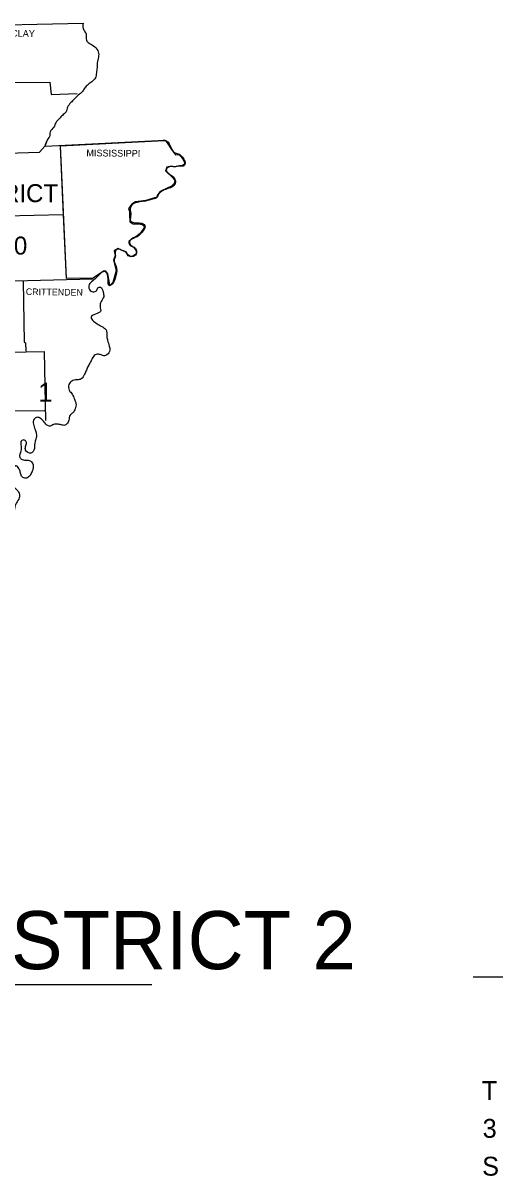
# Model space of a CAD drawing. Extents: x -42408 to 34530, y -43140 to 20491.
# Drawn here: x 4174 to 5698, y -23873 to -20216 of the extents above; entities that cross this region are included whole.
import ezdxf

# ---------------------------------------------------------------- set-up
doc = ezdxf.new("R2010")
doc.units = 0
for name, color, linetype in [('1', 7, 'Continuous'), ('2', 7, 'Continuous'), ('3', 7, 'Continuous'), ('Default', 7, 'Continuous')]:
    doc.layers.add(name, color=color, linetype=linetype)

msp = doc.modelspace()

# ---------------------------------------------------------------- linework, layer by layer
at = {"layer": '1'}
for p, q in [((4244.5, -20607.1), (4250.5, -20588.6)), ((4246, -20601.1), (4252, -20586.6)), ((4292.9, -20605.3), (4622.3, -20589)), ((4622.3, -20589), (4625.1, -20588.9)), ((4625.1, -20588.9), (4627.5, -20590.5)), ((4627.5, -20590.5), (4633.8, -20599.7)), ((4312.5, -21026.2), (4292.9, -20605.3)), ((4633.8, -20599.7), (4645.8, -20617)), ((4645.8, -20617), (4657.8, -20634.3)), ((4657.8, -20634.3), (4663.8, -20632.6)), ((4663.8, -20632.6), (4670, -20633.7)), ((4670, -20633.7), (4675.5, -20639.3)), ((4675.5, -20639.3), (4681.8, -20647.7)), ((4681.8, -20647.7), (4686.5, -20656.9)), ((4686.5, -20656.9), (4686.6, -20664)), ((4629.1, -20676.1), (4626.7, -20685.3)), ((4626.7, -20685.3), (4650.8, -20707.7)), ((4631.1, -20673.3), (4629.1, -20676.1)), ((4644, -20670.5), (4631.1, -20673.3)), ((4654.6, -20671.7), (4644, -20670.5)), ((4670.7, -20668.5), (4654.6, -20671.7)), ((4680.4, -20668.4), (4670.7, -20668.5)), ((4686.6, -20664), (4680.4, -20668.4)), ((4645.9, -20733.8), (4613.3, -20748.2)), ((4654.1, -20725.5), (4645.9, -20733.8)), ((4650.8, -20707.7), (4656.3, -20715.9)), ((4656.3, -20715.9), (4654.1, -20725.5)), ((4598.5, -20768.7), (4564.5, -20779.4)), ((4601, -20761.3), (4598.5, -20768.7)), ((4606.9, -20753.7), (4601, -20761.3)), ((4613.3, -20748.2), (4606.9, -20753.7)), ((4519.5, -20790.2), (4509.5, -20804.3)), ((4509.5, -20804.3), (4512.6, -20813.5)), ((4530.9, -20783), (4519.5, -20790.2)), ((4564.5, -20779.4), (4530.9, -20783)), ((4512.6, -20813.5), (4512.6, -20823.1)), ((4512.6, -20823.1), (4513.5, -20847)), ((4513.5, -20847), (4523.6, -20853)), ((4523.6, -20853), (4535.3, -20853.4)), ((4535.3, -20853.4), (4547, -20853.8)), ((4560.1, -20863.4), (4545.8, -20883.9)), ((4547, -20853.8), (4551.3, -20853.9)), ((4551.3, -20853.9), (4556.8, -20858)), ((4556.8, -20858), (4560.1, -20863.4)), ((4523.5, -20897.9), (4510, -20908.8)), ((4510, -20908.8), (4510.5, -20913.9)), ((4510.5, -20913.9), (4514.6, -20921.7)), ((4532.3, -20894.1), (4523.5, -20897.9)), ((4545.8, -20883.9), (4532.3, -20894.1)), ((4466.2, -20953.4), (4461.1, -20967.9)), ((4475.7, -20931.3), (4463.8, -20939)), ((4463.8, -20939), (4464.4, -20944.8)), ((4464.4, -20944.8), (4466.2, -20953.4)), ((4487.1, -20936), (4475.7, -20931.3)), ((4501.9, -20942.1), (4487.1, -20936)), ((4506.8, -20951), (4501.9, -20942.1)), ((4515.7, -20956.1), (4506.8, -20951)), ((4514.6, -20921.7), (4524.5, -20927.2)), ((4522.8, -20955.8), (4515.7, -20956.1)), ((4531.7, -20950), (4522.8, -20955.8)), ((4524.5, -20927.2), (4532.1, -20936.3)), ((4534.7, -20943.6), (4531.7, -20950)), ((4532.1, -20936.3), (4534.7, -20943.6)), ((4461.1, -20967.9), (4470, -21001.1)), ((4397.1, -21025.6), (4312.5, -21026.2)), ((4429.3, -21002.7), (4397.1, -21025.6)), ((4436.5, -21003.2), (4429.3, -21002.7)), ((4443.1, -21011.3), (4436.5, -21003.2)), ((4449.3, -21047.7), (4443.1, -21011.3)), ((4470, -21001.1), (4459.5, -21038.6)), ((4452.1, -21046.7), (4449.3, -21047.7)), ((4459.5, -21038.6), (4452.1, -21046.7))]:
    msp.add_line(p, q, dxfattribs=at)
for points in [[(1618, -20239.1), (2427.6, -20239.6), (3138, -20238.1), (3976.1, -20225.1), (4364.6, -20216.1)], [(3964, -20497.1), (3966.6, -20405.3), (3966.6, -20405.3), (4259.5, -20403.8), (4263.5, -20442.9), (4346.1, -20439.9)], [(4244.5, -20607.1), (4624.5, -20587.6)], [(3949.1, -20634.6), (4227, -20625.6), (4243.5, -20606.6)], [(4292.5, -20607.6), (4301.1, -20824.4), (4311.1, -21026.1)], [(4301.1, -20824.4), (3839.9, -20834.9)], [(3843.9, -21037.7), (4037.2, -21036.7), (4037.7, -21029.7), (4104.8, -21024.6), (4104.8, -21035.2), (4396.2, -21027.1)], [(4174.9, -21035.2), (4177.4, -21227.9), (4181.9, -21230.9), (4183.4, -21257)], [(3843.9, -21265.5), (4241.5, -21257.5)], [(4241.5, -21257.5), (4245.5, -21476.7)], [(3843.9, -21891.3), (3883, -21888.8), (3882.5, -21787.2), (3845.9, -21784.7), (3847.9, -21585.9), (3816.4, -21581.4), (3815.4, -21447.7), (4242.5, -21444.7)]]:
    msp.add_lwpolyline(points, dxfattribs=at)
for points in [[(4364.6, -20216.1), (4367.1, -20238.1), (4374.1, -20249.6), (4375.2, -20270.6), (4383.7, -20279.6), (4398.2, -20288.7), (4411.2, -20303.2), (4414.2, -20320.2), (4410.2, -20337.7), (4409.2, -20357.3), (4407.2, -20374.3), (4404.2, -20389.8), (4392.2, -20402.3), (4380.7, -20411.3), (4370.1, -20421.8), (4362.6, -20432.9), (4349.6, -20444.9), (4336.6, -20457.4), (4326.1, -20468.4), (4315.6, -20482.4), (4310.6, -20497.9), (4299, -20509), (4290, -20519), (4278, -20532.5), (4272, -20546), (4260.5, -20561.5), (4258, -20576.5), (4250.5, -20588.6), (4250, -20590.6)], [(4619, -20588.1), (4624.5, -20587.6), (4641.5, -20605.6), (4649, -20620.6), (4660, -20629.1), (4672.5, -20633.6), (4682.1, -20645.1), (4688.6, -20657.7), (4685.1, -20668.7), (4671, -20669.7), (4655.5, -20672.2), (4640.5, -20671.7), (4628.5, -20681.7), (4639.5, -20695.2), (4654, -20707.7), (4658, -20721.2), (4650, -20734.3), (4634, -20741.3), (4618.5, -20747.3), (4604.5, -20759.3), (4597.9, -20770.8), (4582.4, -20775.8), (4566.4, -20780.3), (4552.4, -20781.8), (4536.4, -20784.8), (4520.8, -20792.3), (4514.3, -20805.4), (4516.3, -20823.9), (4515.8, -20843.4), (4532.4, -20849.9), (4546.9, -20850.4), (4560.9, -20857.9), (4559.4, -20868.9), (4548.9, -20883), (4536.4, -20894), (4523.8, -20899.5), (4512.3, -20910), (4516.3, -20920.5), (4526.9, -20927.5), (4534.4, -20939), (4533.4, -20949.5), (4521.3, -20957.1), (4508.3, -20954), (4498.8, -20941.5), (4487.8, -20937.5), (4478.3, -20933), (4467.3, -20939.5), (4467.3, -20954), (4463.3, -20969.6), (4466.8, -20981.1), (4471.3, -20997.1), (4470.8, -21009.1), (4466.8, -21026.1), (4458.3, -21043.7), (4448.2, -21049.2), (4444.2, -21030.2), (4442.2, -21014.6), (4436.2, -21005.6), (4428.2, -21005.1), (4417.7, -21012.6), (4406.2, -21024.1), (4391.7, -21036.7), (4383.2, -21049.2), (4387.7, -21064.7), (4398.7, -21068.7), (4407.2, -21065.7), (4411.7, -21055.7), (4420.2, -21054.2), (4428.2, -21069.7)], [(4428.2, -21069.7), (4430.2, -21084.2), (4421.7, -21099.7), (4418.7, -21115.3), (4420.2, -21130.8), (4404.2, -21139.3), (4390.2, -21149.3), (4398.2, -21161.3), (4413.2, -21172.3), (4428.2, -21180.9), (4437.7, -21189.4), (4440.2, -21209.9), (4442.7, -21222.9), (4447.7, -21240.9), (4449.8, -21253.4), (4440.7, -21268.5), (4430.2, -21271.5), (4419.2, -21268), (4406.2, -21267), (4395.7, -21277), (4388.2, -21291), (4380.7, -21305), (4375.2, -21317), (4369.6, -21330.1), (4358.6, -21345.1), (4345.1, -21347.6), (4329.1, -21351.6), (4319.6, -21362.6), (4321.1, -21381.1), (4330.1, -21393.6), (4337.1, -21409.2), (4342.1, -21422.7), (4339.6, -21439.7), (4332.6, -21452.2), (4323.6, -21459.7), (4319.6, -21475.7), (4313.1, -21487.8), (4307.1, -21491.8), (4295, -21490.8), (4282, -21488.3), (4271, -21489.3), (4260.5, -21494.8), (4250, -21491.3), (4239, -21479.3), (4230, -21470.2), (4219.9, -21466.7), (4209.4, -21472.2), (4207.4, -21488.8), (4212.4, -21505.8), (4216.9, -21528.8), (4212.4, -21542.8), (4210.9, -21565.9)], [(4210.9, -21565.9), (4199.4, -21580.4), (4182.4, -21571.4), (4182.4, -21559.4), (4184.9, -21546.8), (4178.9, -21538.8), (4168.4, -21542.3), (4168.4, -21557.9), (4167.4, -21572.9), (4164.4, -21594.4), (4171.4, -21600.9), (4187.4, -21602.9), (4198.9, -21605.9), (4205.9, -21617.4), (4205.4, -21631.5), (4199.9, -21645), (4191.9, -21656), (4179.4, -21660), (4169.4, -21653.5), (4165.4, -21640.5), (4160.9, -21628.9), (4152.4, -21620.4), (4143.3, -21630), (4141.3, -21647.5), (4141.8, -21662.5), (4141.8, -21683), (4154.9, -21696.5), (4162.9, -21712.1), (4160.4, -21726.1), (4150.9, -21742.6), (4146.8, -21757.1), (4142.8, -21776.6), (4143.3, -21798.2), (4139.8, -21819.2), (4132.8, -21833.2), (4119.8, -21844.7), (4111.3, -21852.2), (4104.3, -21859.8), (4100.8, -21874.8), (4098.3, -21885.3), (4088.8, -21897.8), (4081.3, -21898.8), (4075.3, -21893.8), (4073.2, -21885.3), (4073.2, -21876.8), (4069.2, -21868.3), (4056.7, -21864.8), (4046.7, -21865.3), (4042.2, -21872.3), (4048.7, -21891.8), (4051.2, -21904.3), (4047.7, -21921.3), (4049.7, -21923.3), (4031.7, -21932.9), (4017.2, -21934.4), (4005.2, -21937.9), (3993.6, -21945.4), (3988.1, -21956.4), (3980.1, -21965.4), (3973.1, -21973.9), (3963.6, -21977.9), (3953.1, -21975.9), (3939.1, -21974.4), (3931.1, -21984.4), (3933.6, -21998.9), (3943.1, -22007.5), (3957.1, -22011.5), (3971.6, -22010.5), (3985.6, -22009), (3998.6, -22016), (3996.1, -22029.5), (3983.6, -22036), (3965.1, -22038), (3950.1, -22036.5), (3932.1, -22040.5), (3923, -22052), (3928.1, -22069.5), (3947.6, -22076.5), (3956.6, -22093.1), (3957.1, -22108.6), (3950.6, -22129.1), (3941.6, -22138.6), (3924, -22142.6), (3910.5, -22145.1), (3908.5, -22168.2), (3902.5, -22179.7), (3892, -22183.2), (3877, -22175.7), (3868, -22172.2), (3857, -22167.2), (3842.9, -22158.7), (3832.4, -22160.2), (3835.4, -22182.2), (3836.4, -22183.2), (3848.4, -22199.7), (3860.5, -22212.7), (3866, -22228.2)]]:
    msp.add_spline(points, degree=3, dxfattribs=at)
at = {"layer": '2'}
msp.add_line((1233.5, -23266.2), (4582.8, -23266.2), dxfattribs=at)
at = {"layer": 'Default'}
msp.add_line((5697.6, -23243.2), (5602.6, -23243.2), dxfattribs=at)

# ---------------------------------------------------------------- texts
at = {"layer": '1'}
msp.add_text('1', height=60.1, dxfattribs=at).set_placement((4222.9, -21417.2))
at = {"layer": '2'}
for s, height, rotation, p in [('CLAY', 21.52, 359.2258, (4136.3, -20259.1)), ('MISSISSIPPI', 21.524, 359.3097, (4375.2, -20638.6)), ('CRITTENDEN', 21.03, 359.213, (4182.9, -21078.7))]:
    msp.add_text(s, height=height, rotation=rotation, dxfattribs=at).set_placement(p)
for s, height, p in [('ARKANSAS HIGHWAY DISTRICT 2', 184.218, (1233.5, -23217.5)), ('T', 60, (5630.5, -23632.5)), ('3', 60, (5633.1, -23752.5)), ('S', 60, (5631.6, -23872.5))]:
    msp.add_text(s, height=height, dxfattribs=at).set_placement(p)
at = {"layer": '3'}
for s, p in [('DISTRICT', (3933.6, -20784.3)), ('10', (4102.8, -20950.5))]:
    msp.add_text(s, height=57.08, dxfattribs=at).set_placement(p)

doc.saveas('drawing.dxf')
